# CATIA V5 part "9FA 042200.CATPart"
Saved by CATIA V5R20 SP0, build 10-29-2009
Part number: 9FA 042200
Revision: ANY
Definition: UNKNOWN
Nomenclature: 9FA 042200
Source: Unknown
Bounding box of the stored display mesh (mm): x -2 to 2, y 0.1 to 12.1, z -2 to 2
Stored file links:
  C:\Users\Utente\Desktop\IO LAVORO\3D X SITO CF\CUMSA\3D files FA\FA 042200\9FA 042200.CATPart

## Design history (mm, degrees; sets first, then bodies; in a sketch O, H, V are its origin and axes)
Body1 "Cortar-Extruir2" (main body)
  Solid1: solid without history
